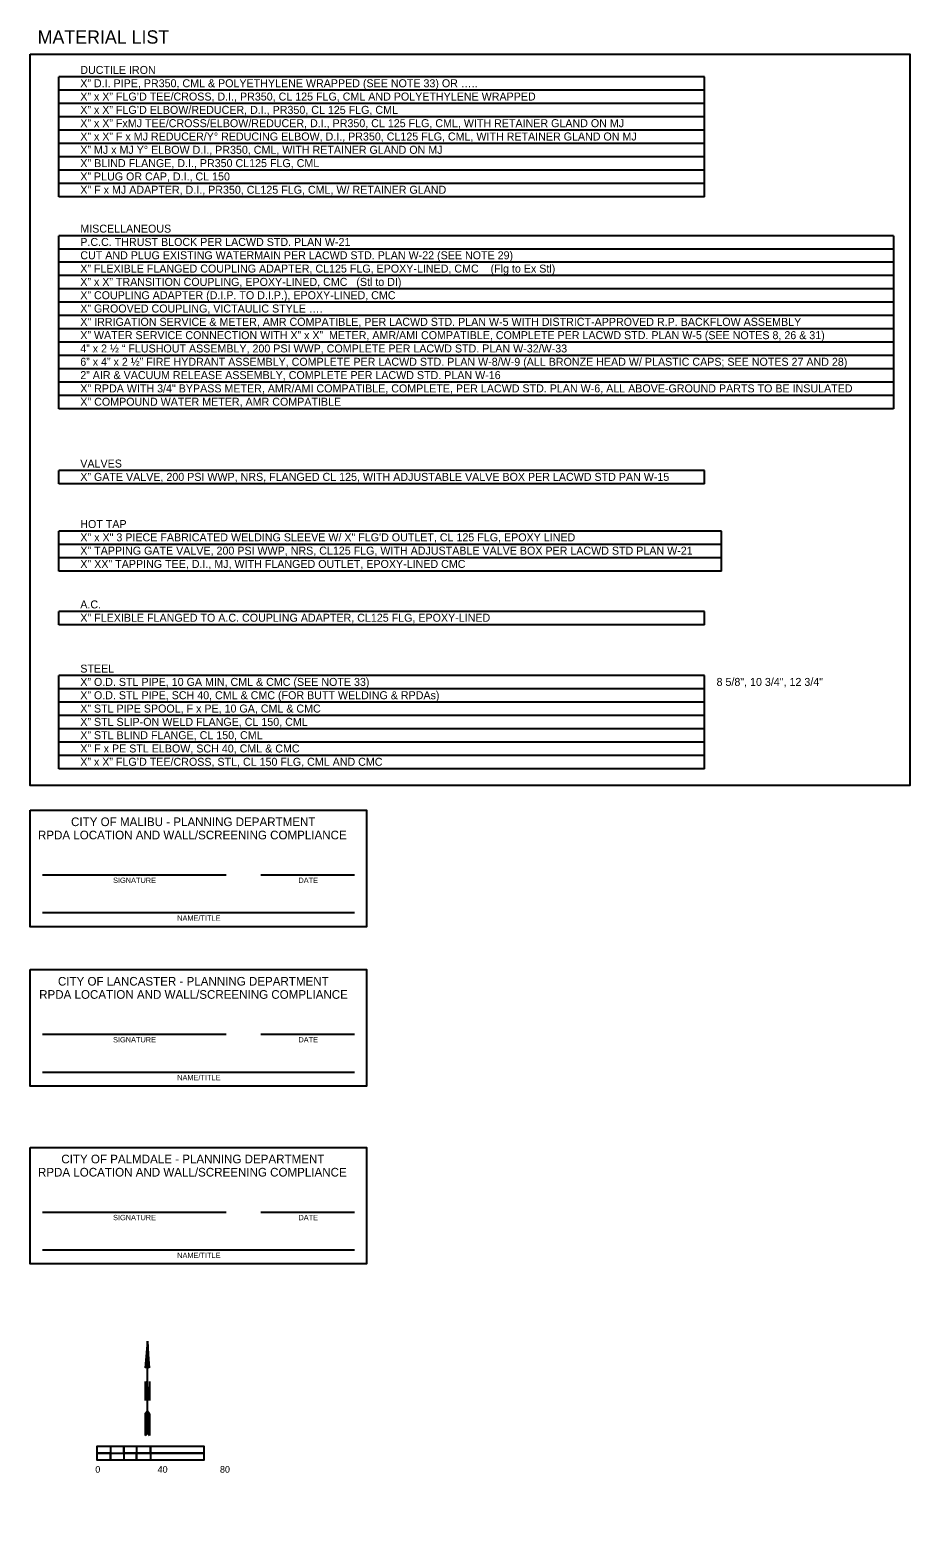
# Model space of a CAD drawing. Extents: x 837 to 1117, y 1316 to 1424.
# Drawn here: x 880.54 to 893.75, y 1401.27 to 1423.92 of the extents above; entities that cross this region are included whole.
import ezdxf

# ---------------------------------------------------------------- set-up
doc = ezdxf.new("R2010")
doc.units = 0
for name, color, linetype in [('BASEMAP', 7, 'Continuous'), ('LLINES', 7, 'Continuous'), ('TEXT', 7, 'Continuous')]:
    doc.layers.add(name, color=color, linetype=linetype)

# ---------------------------------------------------------------- blocks, each defined once
blk = doc.blocks.new('_U0')
at = {"layer": 'LLINES'}
for p, q in [((0, 1378), (-79, 591)), ((0, 1378), (-64, 606)), ((0, 1378), (-49, 620)), ((0, 1378), (-35, 634)), ((0, 1378), (-22, 647)), ((0, 1378), (-9, 660)), ((79, 591), (0, 1378)), ((0, 1378), (4, 666)), ((0, 1378), (43, 626)), ((0, 1378), (57, 612)), ((0, 1378), (29, 640)), ((2, 1302), (16, 653)), ((-79, 591), (0, 669)), ((0, 39), (0, 669)), ((0, 669), (79, 591)), ((16, 654), (29, 642)), ((-79, 197), (79, -118)), ((-79, 197), (-79, -354)), ((-79, 189), (79, -126)), ((-79, 181), (79, -134)), ((-79, 173), (79, -142)), ((-79, 165), (79, -150)), ((-79, 157), (79, -157)), ((-79, 150), (79, -165)), ((-79, 142), (79, -173)), ((-79, 134), (79, -181)), ((-79, 126), (79, -189)), ((-79, 118), (79, -197)), ((-79, 110), (79, -205)), ((-79, 102), (79, -213)), ((-79, 94), (79, -220)), ((-79, 87), (79, -228)), ((-79, 79), (79, -236)), ((-79, 71), (79, -244)), ((-79, 63), (79, -252)), ((-79, 55), (79, -260)), ((-79, 47), (79, -268)), ((-79, 39), (79, -276)), ((-79, 31), (79, -283)), ((-79, 24), (79, -291)), ((-79, 16), (79, -299)), ((-79, 8), (79, -307)), ((79, 197), (79, -354)), ((-79, 0), (79, -315)), ((-79, -8), (79, -323)), ((-79, -16), (79, -331)), ((-79, -24), (79, -339)), ((-79, -31), (79, -346)), ((-79, -39), (79, -354)), ((-79, -39), (79, -354)), ((0, -669), (0, -197)), ((0, -669), (-79, -748)), ((0, -669), (-79, -748)), ((0, -669), (-79, -748)), ((-79, -748), (-79, -1378)), ((-79, -748), (-79, -1378)), ((-79, -748), (-79, -1378)), ((-71, -748), (-71, -740)), ((-71, -748), (-71, -1370)), ((-63, -748), (-63, -732)), ((-63, -748), (-63, -1362)), ((-55, -748), (-55, -724)), ((-55, -748), (-55, -1354)), ((-47, -748), (-47, -717)), ((-47, -748), (-47, -1346)), ((-39, -748), (-39, -709)), ((-39, -748), (-39, -1339)), ((-31, -748), (-31, -701)), ((-31, -748), (-31, -1331)), ((-24, -748), (-24, -693)), ((-24, -748), (-24, -1323)), ((-16, -748), (-16, -685)), ((-16, -748), (-16, -1315)), ((-8, -748), (-8, -677)), ((-8, -748), (-8, -1307)), ((-8, -748), (-8, -1307)), ((0, -748), (0, -631)), ((79, -748), (0, -669)), ((0, -748), (0, -1299)), ((8, -748), (8, -677)), ((8, -748), (8, -1307)), ((16, -748), (16, -685)), ((16, -748), (16, -1315)), ((24, -748), (24, -693)), ((24, -748), (24, -1323)), ((31, -748), (31, -701)), ((31, -748), (31, -1331)), ((39, -748), (39, -709)), ((39, -748), (39, -1339)), ((47, -748), (47, -717)), ((47, -748), (47, -1346)), ((55, -748), (55, -724)), ((55, -748), (55, -1354)), ((63, -748), (63, -732)), ((63, -748), (63, -1362)), ((71, -748), (71, -740)), ((71, -748), (71, -1370)), ((79, -1378), (79, -748)), ((79, -748), (79, -1378)), ((-79, -1378), (0, -1299)), ((0, -1299), (79, -1378))]:
    blk.add_line(p, q, dxfattribs=at)
blk = doc.blocks.new('_U8')
at = {"layer": 'LLINES'}
for p, q in [((-2.295, -1.877), (1.489, 2.511)), ((-0.692, 0.559), (-0.114, 0.074)), ((-1.185, -0.013), (-0.626, -0.481)), ((-2.111, -1.086), (-1.533, -1.571))]:
    blk.add_line(p, q, dxfattribs=at)
for points in [[(-2.584, -1.635), (1.2, 2.753), (1.778, 2.268), (-2.006, -2.12)], [(-0.692, 0.559), (1.2, 2.753), (1.489, 2.511), (-0.403, 0.317)], [(-0.915, -0.239), (-0.422, 0.333), (-0.114, 0.074), (-0.607, -0.498)], [(-1.822, -1.329), (-1.349, -0.78), (-1.06, -1.023), (-1.533, -1.571)], [(-1.638, -0.538), (-1.185, -0.013), (-0.903, -0.249), (-1.356, -0.774)], [(-1.822, -1.329), (-2.295, -1.877), (-2.584, -1.635), (-2.111, -1.086)]]:
    blk.add_lwpolyline(points, close=True, dxfattribs=at)
blk.add_lwpolyline([(-2.584, -1.635), (-1.638, -0.538), (-1.06, -1.023)], dxfattribs=at)
blk.add_text('0                       40                     80', height=0.36477, rotation=49.23155, dxfattribs=at).set_placement((-1.549, -2.642))
blk = doc.blocks.new('_U3')
at = {"layer": 'BASEMAP'}
for p, q in [((-2.343, 0.365), (0.416, 0.365)), ((0.936, 0.365), (2.343, 0.365)), ((-2.343, -0.203), (2.343, -0.203))]:
    blk.add_line(p, q, dxfattribs=at)
at = {"layer": 'TEXT'}
for s, p in [('SIGNATURE', (-1.281, 0.243)), ('DATE', (1.503, 0.243)), ('NAME/TITLE', (-0.318, -0.325))]:
    blk.add_text(s, height=0.08, dxfattribs=at).set_placement(p)
blk = doc.blocks.new('_U5')
at = {"layer": 'BASEMAP'}
for p, q in [((-2.343, 0.365), (0.416, 0.365)), ((0.936, 0.365), (2.343, 0.365)), ((-2.343, -0.203), (2.343, -0.203))]:
    blk.add_line(p, q, dxfattribs=at)
at = {"layer": 'TEXT'}
for s, p in [('SIGNATURE', (-1.281, 0.243)), ('DATE', (1.503, 0.243)), ('NAME/TITLE', (-0.318, -0.325))]:
    blk.add_text(s, height=0.08, dxfattribs=at).set_placement(p)
blk = doc.blocks.new('_U7')
at = {"layer": 'BASEMAP'}
for p, q in [((-2.343, 0.365), (0.416, 0.365)), ((0.936, 0.365), (2.343, 0.365)), ((-2.343, -0.203), (2.343, -0.203))]:
    blk.add_line(p, q, dxfattribs=at)
at = {"layer": 'TEXT'}
for s, p in [('SIGNATURE', (-1.281, 0.243)), ('DATE', (1.503, 0.243)), ('NAME/TITLE', (-0.318, -0.325))]:
    blk.add_text(s, height=0.08, dxfattribs=at).set_placement(p)

msp = doc.modelspace()

# ---------------------------------------------------------------- linework, layer by layer
at = {"layer": 'BASEMAP'}
for p, q in [((890.667, 1423.212), (880.972, 1423.212)), ((880.972, 1423.012), (880.972, 1423.212)), ((890.667, 1423.012), (880.972, 1423.012)), ((880.972, 1422.812), (880.972, 1423.012)), ((890.667, 1423.012), (890.667, 1423.212)), ((890.667, 1422.812), (890.667, 1423.012)), ((890.667, 1422.812), (880.972, 1422.812)), ((880.972, 1422.612), (880.972, 1422.812)), ((890.667, 1422.612), (890.667, 1422.812)), ((890.667, 1422.612), (880.972, 1422.612)), ((880.972, 1422.412), (880.972, 1422.612)), ((890.667, 1422.412), (890.667, 1422.612)), ((890.667, 1422.412), (880.972, 1422.412)), ((880.972, 1422.212), (880.972, 1422.412)), ((890.667, 1422.212), (890.667, 1422.412)), ((890.667, 1422.212), (880.972, 1422.212)), ((880.972, 1422.012), (880.972, 1422.212)), ((890.667, 1422.012), (890.667, 1422.212)), ((890.667, 1422.012), (880.972, 1422.012)), ((880.972, 1421.812), (880.972, 1422.012)), ((890.667, 1421.812), (890.667, 1422.012)), ((890.667, 1421.812), (880.972, 1421.812)), ((880.972, 1421.612), (880.972, 1421.812)), ((890.667, 1421.612), (890.667, 1421.812)), ((890.667, 1421.612), (880.972, 1421.612)), ((880.972, 1421.412), (880.972, 1421.612)), ((890.667, 1421.412), (880.972, 1421.412)), ((890.667, 1421.412), (890.667, 1421.612)), ((893.508, 1420.828), (880.972, 1420.828)), ((880.972, 1420.628), (880.972, 1420.828)), ((893.508, 1420.828), (893.508, 1418.228)), ((893.508, 1420.628), (880.972, 1420.628)), ((880.972, 1420.428), (880.972, 1420.628)), ((893.508, 1420.428), (880.972, 1420.428)), ((880.972, 1420.228), (880.972, 1420.428)), ((893.508, 1420.228), (880.972, 1420.228)), ((880.972, 1420.028), (880.972, 1420.228)), ((893.508, 1420.028), (880.972, 1420.028)), ((880.972, 1419.828), (880.972, 1420.028)), ((893.508, 1419.828), (880.972, 1419.828)), ((880.972, 1419.628), (880.972, 1419.828)), ((893.508, 1419.628), (880.972, 1419.628)), ((880.972, 1419.428), (880.972, 1419.628)), ((893.508, 1419.428), (880.972, 1419.428)), ((880.972, 1419.228), (880.972, 1419.428)), ((893.508, 1419.228), (880.972, 1419.228)), ((880.972, 1419.028), (880.972, 1419.228)), ((893.508, 1419.028), (880.972, 1419.028)), ((880.972, 1418.828), (880.972, 1419.028)), ((893.508, 1418.828), (880.972, 1418.828)), ((880.972, 1418.628), (880.972, 1418.828)), ((893.508, 1418.628), (880.972, 1418.628)), ((880.972, 1418.428), (880.972, 1418.628)), ((893.508, 1418.428), (880.972, 1418.428)), ((880.972, 1418.228), (880.972, 1418.428)), ((893.508, 1418.228), (880.972, 1418.228)), ((890.667, 1417.299), (880.972, 1417.299)), ((880.972, 1417.099), (880.972, 1417.299)), ((890.667, 1417.099), (890.667, 1417.299)), ((890.667, 1417.099), (880.972, 1417.099)), ((890.923, 1416.391), (880.972, 1416.391)), ((880.972, 1416.191), (880.972, 1416.391)), ((890.923, 1416.191), (890.923, 1416.391)), ((890.923, 1416.191), (880.972, 1416.191)), ((880.972, 1415.991), (880.972, 1416.191)), ((890.923, 1415.991), (880.972, 1415.991)), ((880.972, 1415.791), (880.972, 1415.991)), ((890.923, 1415.991), (890.923, 1416.191)), ((890.923, 1415.791), (890.923, 1415.991)), ((890.923, 1415.791), (880.972, 1415.791)), ((890.667, 1415.183), (880.972, 1415.183)), ((880.972, 1414.983), (880.972, 1415.183)), ((890.667, 1414.983), (890.667, 1415.183)), ((890.667, 1414.983), (880.972, 1414.983)), ((890.667, 1414.219), (880.972, 1414.219)), ((880.972, 1414.019), (880.972, 1414.219)), ((890.667, 1414.019), (890.667, 1414.219)), ((890.667, 1414.019), (880.972, 1414.019)), ((880.972, 1413.819), (880.972, 1414.019)), ((890.667, 1413.819), (890.667, 1414.019)), ((890.667, 1413.819), (880.972, 1413.819)), ((880.972, 1413.619), (880.972, 1413.819)), ((890.667, 1413.619), (890.667, 1413.819)), ((890.667, 1413.619), (880.972, 1413.619)), ((880.972, 1413.419), (880.972, 1413.619)), ((890.667, 1413.419), (890.667, 1413.619)), ((890.667, 1413.419), (880.972, 1413.419)), ((880.972, 1413.219), (880.972, 1413.419)), ((890.667, 1413.219), (890.667, 1413.419)), ((890.667, 1413.219), (880.972, 1413.219)), ((880.972, 1413.019), (880.972, 1413.219)), ((890.667, 1413.019), (890.667, 1413.219)), ((890.667, 1413.019), (880.972, 1413.019)), ((880.972, 1412.819), (880.972, 1413.019)), ((890.667, 1412.819), (880.972, 1412.819)), ((890.667, 1412.819), (890.667, 1413.019))]:
    msp.add_line(p, q, dxfattribs=at)
for points in [[(880.54, 1423.555), (893.752, 1423.555), (893.752, 1412.567), (880.54, 1412.567)], [(880.54, 1412.199), (885.593, 1412.199), (885.593, 1410.448), (880.54, 1410.448)], [(880.54, 1409.803), (885.593, 1409.803), (885.593, 1408.052), (880.54, 1408.052)], [(880.54, 1407.133), (885.593, 1407.133), (885.593, 1405.382), (880.54, 1405.382)]]:
    msp.add_lwpolyline(points, close=True, dxfattribs=at)

# ---------------------------------------------------------------- block references
for name, p in [('_U3', (883.066, 1410.862)), ('_U5', (883.066, 1408.467)), ('_U7', (883.066, 1405.796))]:
    msp.add_blockref(name, p, dxfattribs=at)
at = {"layer": 'LLINES', "xscale": 0.00041148, "yscale": 0.00051435}
msp.add_blockref('_U0', (882.3, 1403.515), dxfattribs=at)
at = {"layer": 'LLINES', "xscale": 0.2741438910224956, "yscale": 0.27786097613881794, "rotation": -49.61278499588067}
msp.add_blockref('_U8', (882.352, 1402.398), dxfattribs=at)

# ---------------------------------------------------------------- texts
at = {"layer": 'LLINES'}
for s, height, p in [('MATERIAL LIST', 0.2, (880.652, 1423.713)), ('DUCTILE IRON', 0.12, (881.293, 1423.258)), ('X” D.I. PIPE, PR350, CML & POLYETHYLENE WRAPPED (SEE NOTE 33) OR …..', 0.12, (881.293, 1423.058)), ('X” x X” FLG’D TEE/CROSS, D.I., PR350, CL 125 FLG, CML AND POLYETHYLENE WRAPPED', 0.12, (881.293, 1422.858)), ('X” x X” FLG’D ELBOW/REDUCER, D.I., PR350, CL 125 FLG, CML', 0.12, (881.293, 1422.658)), ('X” x X” FxMJ TEE/CROSS/ELBOW/REDUCER, D.I., PR350, CL 125 FLG, CML, WITH RETAINER GLAND ON MJ', 0.12, (881.293, 1422.458)), ('X” x X” F x MJ REDUCER/Y° REDUCING ELBOW, D.I., PR350, CL125 FLG, CML, WITH RETAINER GLAND ON MJ', 0.12, (881.293, 1422.258)), ('X” MJ x MJ Y° ELBOW D.I., PR350, CML, WITH RETAINER GLAND ON MJ', 0.12, (881.293, 1422.058)), ('X" BLIND FLANGE, D.I., PR350 CL125 FLG, CML', 0.12, (881.293, 1421.858)), ('X” PLUG OR CAP, D.I., CL 150', 0.12, (881.293, 1421.658)), ('X" F x MJ ADAPTER, D.I., PR350, CL125 FLG, CML, W/ RETAINER GLAND', 0.12, (881.293, 1421.458)), ('MISCELLANEOUS', 0.12, (881.293, 1420.874)), ('P.C.C. THRUST BLOCK PER LACWD STD. PLAN W-21', 0.12, (881.293, 1420.674)), ('CUT AND PLUG EXISTING WATERMAIN PER LACWD STD. PLAN W-22 (SEE NOTE 29)', 0.12, (881.293, 1420.474)), ('X” FLEXIBLE FLANGED COUPLING ADAPTER, CL125 FLG, EPOXY-LINED, CMC    (Flg to Ex Stl)', 0.12, (881.293, 1420.274)), ('X” x X” TRANSITION COUPLING, EPOXY-LINED, CMC   (Stl to DI)', 0.12, (881.293, 1420.074)), ('X” COUPLING ADAPTER (D.I.P. TO D.I.P.), EPOXY-LINED, CMC', 0.12, (881.293, 1419.874)), ('X” GROOVED COUPLING, VICTAULIC STYLE ….', 0.12, (881.293, 1419.674)), ('X" IRRIGATION SERVICE & METER, AMR COMPATIBLE, PER LACWD STD. PLAN W-5 WITH DISTRICT-APPROVED R.P. BACKFLOW ASSEMBLY', 0.12, (881.293, 1419.474)), ('X” WATER SERVICE CONNECTION WITH X” x X”  METER, AMR/AMI COMPATIBLE, COMPLETE PER LACWD STD. PLAN W-5 (SEE NOTES 8, 26 & 31)', 0.12, (881.293, 1419.274)), ('4” x 2 ½ “ FLUSHOUT ASSEMBLY, 200 PSI WWP, COMPLETE PER LACWD STD. PLAN W-32/W-33', 0.12, (881.293, 1419.074)), ('6” x 4” x 2 ½” FIRE HYDRANT ASSEMBLY, COMPLETE PER LACWD STD. PLAN W-8/W-9 (ALL BRONZE HEAD W/ PLASTIC CAPS; SEE NOTES 27 AND 28)', 0.12, (881.293, 1418.874)), ('2” AIR & VACUUM RELEASE ASSEMBLY, COMPLETE PER LACWD STD. PLAN W-16', 0.12, (881.293, 1418.674)), ('X" RPDA WITH 3/4" BYPASS METER, AMR/AMI COMPATIBLE, COMPLETE, PER LACWD STD. PLAN W-6, ALL ABOVE-GROUND PARTS TO BE INSULATED', 0.12, (881.293, 1418.474)), ('X" COMPOUND WATER METER, AMR COMPATIBLE ', 0.12, (881.293, 1418.274)), ('VALVES', 0.12, (881.293, 1417.345)), ('X” GATE VALVE, 200 PSI WWP, NRS, FLANGED CL 125, WITH ADJUSTABLE VALVE BOX PER LACWD STD PAN W-15', 0.12, (881.293, 1417.145)), ('HOT TAP', 0.12, (881.293, 1416.437)), ('X" x X" 3 PIECE FABRICATED WELDING SLEEVE W/ X" FLG\'D OUTLET, CL 125 FLG, EPOXY LINED', 0.12, (881.293, 1416.237)), ('X" TAPPING GATE VALVE, 200 PSI WWP, NRS, CL125 FLG, WITH ADJUSTABLE VALVE BOX PER LACWD STD PLAN W-21', 0.12, (881.293, 1416.037)), ('X" XX" TAPPING TEE, D.I., MJ, WITH FLANGED OUTLET, EPOXY-LINED CMC', 0.12, (881.293, 1415.837)), ('A.C.', 0.12, (881.293, 1415.229)), ('X" FLEXIBLE FLANGED TO A.C. COUPLING ADAPTER, CL125 FLG, EPOXY-LINED', 0.12, (881.293, 1415.029)), ('X” O.D. STL PIPE, 10 GA MIN, CML & CMC (SEE NOTE 33)', 0.12, (881.293, 1414.065)), ('STEEL', 0.12, (881.293, 1414.265)), ('8 5/8", 10 3/4", 12 3/4"', 0.12, (890.849, 1414.065)), ('X” O.D. STL PIPE, SCH 40, CML & CMC (FOR BUTT WELDING & RPDAs)', 0.12, (881.293, 1413.865)), ('X” STL PIPE SPOOL, F x PE, 10 GA, CML & CMC', 0.12, (881.293, 1413.665)), ('X” STL SLIP-ON WELD FLANGE, CL 150, CML', 0.12, (881.293, 1413.465)), ('X” STL BLIND FLANGE, CL 150, CML', 0.12, (881.293, 1413.265)), ('X" F x PE STL ELBOW, SCH 40, CML & CMC', 0.12, (881.293, 1413.065)), ('X” x X” FLG’D TEE/CROSS, STL, CL 150 FLG, CML AND CMC', 0.12, (881.293, 1412.865))]:
    msp.add_text(s, height=height, dxfattribs=at).set_placement(p)
at = {"layer": 'TEXT'}
for s, p in [('CITY OF MALIBU - PLANNING DEPARTMENT', (881.154, 1411.959)), ('RPDA LOCATION AND WALL/SCREENING COMPLIANCE', (880.657, 1411.76)), ('CITY OF LANCASTER - PLANNING DEPARTMENT', (880.957, 1409.563)), ('RPDA LOCATION AND WALL/SCREENING COMPLIANCE', (880.675, 1409.365)), ('CITY OF PALMDALE - PLANNING DEPARTMENT', (881.008, 1406.893)), ('RPDA LOCATION AND WALL/SCREENING COMPLIANCE', (880.657, 1406.695))]:
    msp.add_text(s, height=0.13, dxfattribs=at).set_placement(p)

doc.saveas('drawing.dxf')
